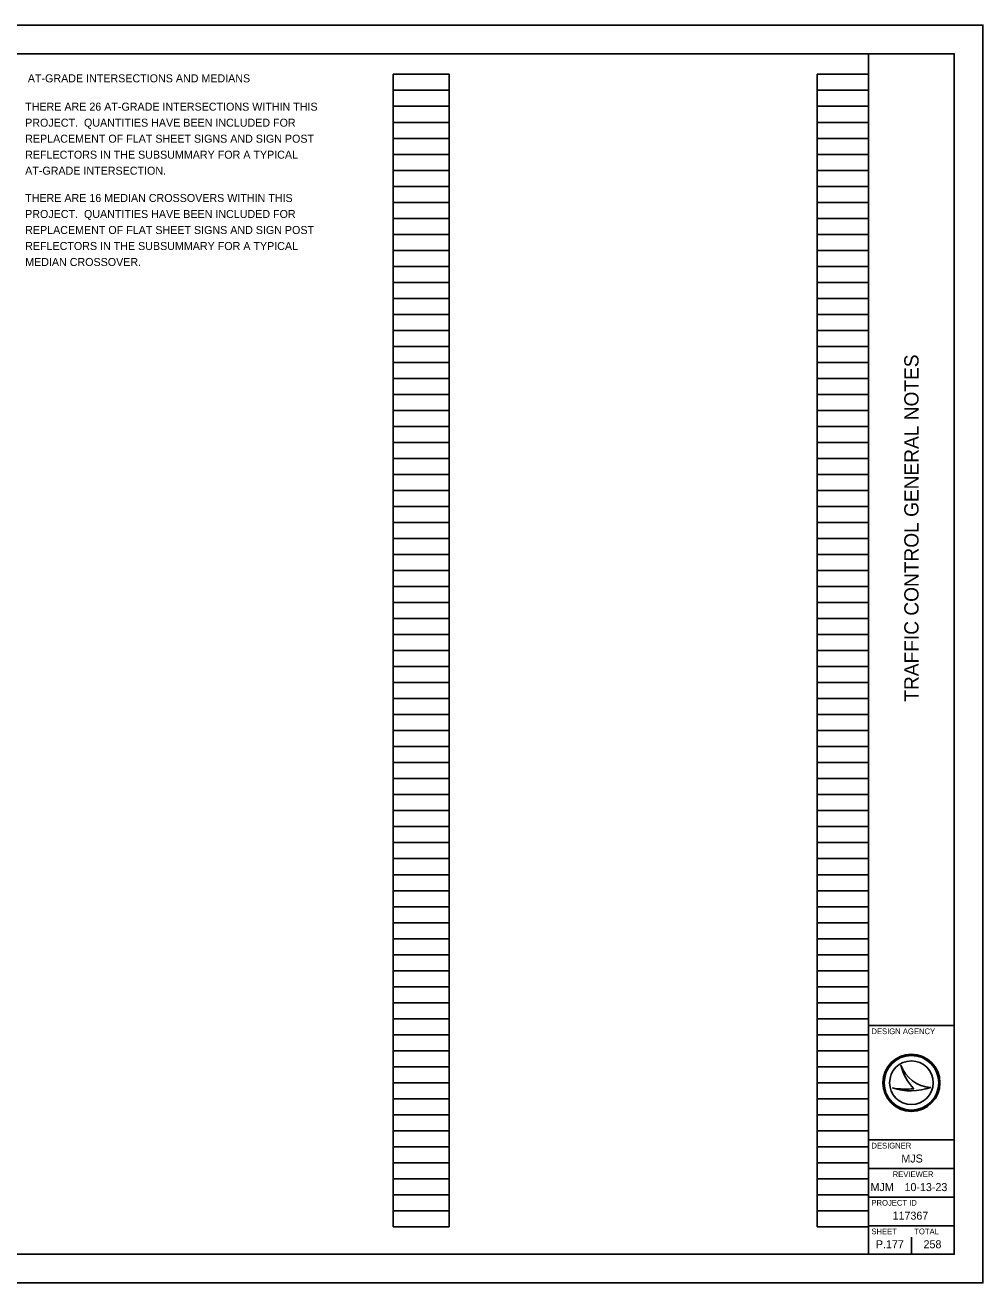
# Model space of a CAD drawing. Extents: x 0 to 34, y 0 to 22.
# Drawn here: x 17.24 to 34, y 0 to 22 of the extents above; entities that cross this region are included whole.
import ezdxf

# ---------------------------------------------------------------- set-up
doc = ezdxf.new("R2010")
doc.units = 0
for name, color, linetype in [('SH_Border', 7, 'Continuous'), ('SH_Cut_Line', 7, 'Continuous'), ('SH_Data', 7, 'Continuous'), ('TX_P_Misc', 7, 'Continuous')]:
    doc.layers.add(name, color=color, linetype=linetype)

msp = doc.modelspace()

# ---------------------------------------------------------------- linework, layer by layer
at = {"layer": 'SH_Border'}
for p, q in [((32, 0.5), (32, 21.5)), ((32, 4.5), (33.5, 4.5)), ((32, 2.5), (33.5, 2.5)), ((32, 2), (33.5, 2)), ((32, 1.5), (33.5, 1.5)), ((32, 1), (33.5, 1))]:
    msp.add_line(p, q, dxfattribs=at)
msp.add_lwpolyline([(1.5, 21.5), (33.5, 21.5), (33.5, 0.5), (1.5, 0.5)], close=True, dxfattribs=at)
at = {"layer": 'SH_Cut_Line'}
msp.add_lwpolyline([(0, 0), (34, 0), (34, 22), (0, 22)], close=True, dxfattribs=at)
at = {"layer": 'SH_Data'}
for p, q in [((23.68, 0.98), (23.68, 21.14)), ((23.68, 21.14), (24.66, 21.14)), ((24.66, 0.98), (24.66, 21.14)), ((31.1, 0.98), (31.1, 21.14)), ((31.1, 21.14), (32, 21.14)), ((32, 0.98), (32, 21.14)), ((23.68, 20.86), (24.66, 20.86)), ((31.1, 20.86), (32, 20.86)), ((23.68, 20.58), (24.66, 20.58)), ((31.1, 20.58), (32, 20.58)), ((23.68, 20.3), (24.66, 20.3)), ((31.1, 20.3), (32, 20.3)), ((23.68, 20.02), (24.66, 20.02)), ((31.1, 20.02), (32, 20.02)), ((23.68, 19.74), (24.66, 19.74)), ((31.1, 19.74), (32, 19.74)), ((23.68, 19.46), (24.66, 19.46)), ((31.1, 19.46), (32, 19.46)), ((23.68, 19.18), (24.66, 19.18)), ((31.1, 19.18), (32, 19.18)), ((23.68, 18.9), (24.66, 18.9)), ((31.1, 18.9), (32, 18.9)), ((23.68, 18.62), (24.66, 18.62)), ((31.1, 18.62), (32, 18.62)), ((23.68, 18.34), (24.66, 18.34)), ((31.1, 18.34), (32, 18.34)), ((23.68, 18.06), (24.66, 18.06)), ((31.1, 18.06), (32, 18.06)), ((23.68, 17.78), (24.66, 17.78)), ((31.1, 17.78), (32, 17.78)), ((23.68, 17.5), (24.66, 17.5)), ((31.1, 17.5), (32, 17.5)), ((23.68, 17.22), (24.66, 17.22)), ((31.1, 17.22), (32, 17.22)), ((23.68, 16.94), (24.66, 16.94)), ((31.1, 16.94), (32, 16.94)), ((23.68, 16.66), (24.66, 16.66)), ((31.1, 16.66), (32, 16.66)), ((23.68, 16.38), (24.66, 16.38)), ((31.1, 16.38), (32, 16.38)), ((23.68, 16.1), (24.66, 16.1)), ((31.1, 16.1), (32, 16.1)), ((23.68, 15.82), (24.66, 15.82)), ((31.1, 15.82), (32, 15.82)), ((23.68, 15.54), (24.66, 15.54)), ((31.1, 15.54), (32, 15.54)), ((23.68, 15.26), (24.66, 15.26)), ((31.1, 15.26), (32, 15.26)), ((23.68, 14.98), (24.66, 14.98)), ((31.1, 14.98), (32, 14.98)), ((23.68, 14.7), (24.66, 14.7)), ((31.1, 14.7), (32, 14.7)), ((23.68, 14.42), (24.66, 14.42)), ((31.1, 14.42), (32, 14.42)), ((23.68, 14.14), (24.66, 14.14)), ((31.1, 14.14), (32, 14.14)), ((23.68, 13.86), (24.66, 13.86)), ((31.1, 13.86), (32, 13.86)), ((23.68, 13.58), (24.66, 13.58)), ((31.1, 13.58), (32, 13.58)), ((23.68, 13.3), (24.66, 13.3)), ((31.1, 13.3), (32, 13.3)), ((23.68, 13.02), (24.66, 13.02)), ((31.1, 13.02), (32, 13.02)), ((23.68, 12.74), (24.66, 12.74)), ((31.1, 12.74), (32, 12.74)), ((23.68, 12.46), (24.66, 12.46)), ((31.1, 12.46), (32, 12.46)), ((23.68, 12.18), (24.66, 12.18)), ((31.1, 12.18), (32, 12.18)), ((23.68, 11.9), (24.66, 11.9)), ((31.1, 11.9), (32, 11.9)), ((23.68, 11.62), (24.66, 11.62)), ((31.1, 11.62), (32, 11.62)), ((23.68, 11.34), (24.66, 11.34)), ((31.1, 11.34), (32, 11.34)), ((23.68, 11.06), (24.66, 11.06)), ((31.1, 11.06), (32, 11.06)), ((23.68, 10.78), (24.66, 10.78)), ((31.1, 10.78), (32, 10.78)), ((23.68, 10.5), (24.66, 10.5)), ((31.1, 10.5), (32, 10.5)), ((23.68, 10.22), (24.66, 10.22)), ((31.1, 10.22), (32, 10.22)), ((23.68, 9.94), (24.66, 9.94)), ((31.1, 9.94), (32, 9.94)), ((23.68, 9.66), (24.66, 9.66)), ((31.1, 9.66), (32, 9.66)), ((23.68, 9.38), (24.66, 9.38)), ((31.1, 9.38), (32, 9.38)), ((23.68, 9.1), (24.66, 9.1)), ((31.1, 9.1), (32, 9.1)), ((23.68, 8.82), (24.66, 8.82)), ((31.1, 8.82), (32, 8.82)), ((23.68, 8.54), (24.66, 8.54)), ((31.1, 8.54), (32, 8.54)), ((23.68, 8.26), (24.66, 8.26)), ((31.1, 8.26), (32, 8.26)), ((23.68, 7.98), (24.66, 7.98)), ((31.1, 7.98), (32, 7.98)), ((23.68, 7.7), (24.66, 7.7)), ((31.1, 7.7), (32, 7.7)), ((23.68, 7.42), (24.66, 7.42)), ((31.1, 7.42), (32, 7.42)), ((23.68, 7.14), (24.66, 7.14)), ((31.1, 7.14), (32, 7.14)), ((23.68, 6.86), (24.66, 6.86)), ((31.1, 6.86), (32, 6.86)), ((23.68, 6.58), (24.66, 6.58)), ((31.1, 6.58), (32, 6.58)), ((23.68, 6.3), (24.66, 6.3)), ((31.1, 6.3), (32, 6.3)), ((23.68, 6.02), (24.66, 6.02)), ((31.1, 6.02), (32, 6.02)), ((23.68, 5.74), (24.66, 5.74)), ((31.1, 5.74), (32, 5.74)), ((23.68, 5.46), (24.66, 5.46)), ((31.1, 5.46), (32, 5.46)), ((23.68, 5.18), (24.66, 5.18)), ((31.1, 5.18), (32, 5.18)), ((23.68, 4.9), (24.66, 4.9)), ((31.1, 4.9), (32, 4.9)), ((23.68, 4.62), (24.66, 4.62)), ((31.1, 4.62), (32, 4.62)), ((23.68, 4.34), (24.66, 4.34)), ((31.1, 4.34), (32, 4.34)), ((23.68, 4.06), (24.66, 4.06)), ((31.1, 4.06), (32, 4.06)), ((23.68, 3.78), (24.66, 3.78)), ((31.1, 3.78), (32, 3.78)), ((32.567, 3.81), (32.567, 3.81)), ((23.68, 3.5), (24.66, 3.5)), ((31.1, 3.5), (32, 3.5)), ((32.417, 3.41), (32.417, 3.41)), ((32.75, 3.5), (32.75, 3.5)), ((33.087, 3.419), (33.087, 3.419)), ((23.68, 3.22), (24.66, 3.22)), ((31.1, 3.22), (32, 3.22)), ((23.68, 2.94), (24.66, 2.94)), ((31.1, 2.94), (32, 2.94)), ((23.68, 2.66), (24.66, 2.66)), ((31.1, 2.66), (32, 2.66)), ((23.68, 2.38), (24.66, 2.38)), ((31.1, 2.38), (32, 2.38)), ((23.68, 2.1), (24.66, 2.1)), ((31.1, 2.1), (32, 2.1)), ((23.68, 1.82), (24.66, 1.82)), ((31.1, 1.82), (32, 1.82)), ((23.68, 1.54), (24.66, 1.54)), ((31.1, 1.54), (32, 1.54)), ((23.68, 1.26), (24.66, 1.26)), ((31.1, 1.26), (32, 1.26)), ((23.68, 0.98), (24.66, 0.98)), ((31.1, 0.98), (32, 0.98)), ((32.375, 0.675), (32.375, 0.675)), ((32.75, 0.5), (32.75, 0.8))]:
    msp.add_line(p, q, dxfattribs=at)
for radius in [0.5, 0.477, 0.477, 0.382]:
    msp.add_circle((32.75, 3.5), radius, dxfattribs=at)
for centre, radius, start, end in [((33.116, 3.998), 0.58, 198.9257, 198.9319), ((33.347, 3.97), 0.796, 191.6379, 191.6421), ((33.116, 3.998), 0.58, 198.9319, 267.1657), ((33.347, 3.97), 0.796, 191.6421, 226.0947), ((32.739, 4.37), 1.013, 251.4576, 290.0832), ((32.648, 4.654), 1.266, 259.4964, 259.4995), ((32.739, 4.37), 1.013, 251.4527, 251.4576), ((32.648, 4.654), 1.266, 259.4995, 276.6672)]:
    msp.add_arc(centre, radius, start, end, dxfattribs=at)

# ---------------------------------------------------------------- texts
msp.add_text('TRAFFIC CONTROL GENERAL NOTES', height=0.25, rotation=90, dxfattribs=at).set_placement((32.875, 10.166))
for s, height, p in [('DESIGN AGENCY', 0.1, (32.05, 4.35)), ('DESIGNER', 0.1, (32.05, 2.35)), ('MJS', 0.14, (32.574, 2.105)), ('REVIEWER', 0.1, (32.422, 1.85)), ('MJM', 0.14, (32.035, 1.605)), ('10-13-23', 0.14, (32.629, 1.605)), ('PROJECT ID', 0.1, (32.05, 1.35)), ('117367', 0.14, (32.42, 1.105)), ('SHEET', 0.1, (32.05, 0.85)), ('TOTAL', 0.1, (32.8, 0.85)), ('P.177', 0.14, (32.128, 0.605)), ('258', 0.14, (32.962, 0.605))]:
    msp.add_text(s, height=height, dxfattribs=at).set_placement(p)
at = {"layer": 'TX_P_Misc'}
for s, p in [('AT-GRADE INTERSECTIONS AND MEDIANS', (17.288, 21)), ('THERE ARE 26 AT-GRADE INTERSECTIONS WITHIN THIS', (17.241, 20.504)), ('PROJECT.  QUANTITIES HAVE BEEN INCLUDED FOR', (17.241, 20.224)), ('REPLACEMENT OF FLAT SHEET SIGNS AND SIGN POST', (17.241, 19.944)), ('REFLECTORS IN THE SUBSUMMARY FOR A TYPICAL', (17.241, 19.664)), ('AT-GRADE INTERSECTION.', (17.241, 19.384)), ('THERE ARE 16 MEDIAN CROSSOVERS WITHIN THIS', (17.241, 18.907)), ('PROJECT.  QUANTITIES HAVE BEEN INCLUDED FOR', (17.241, 18.627)), ('REPLACEMENT OF FLAT SHEET SIGNS AND SIGN POST', (17.241, 18.347)), ('REFLECTORS IN THE SUBSUMMARY FOR A TYPICAL', (17.241, 18.067)), ('MEDIAN CROSSOVER.', (17.241, 17.787))]:
    msp.add_text(s, height=0.14, dxfattribs=at).set_placement(p)

doc.saveas('drawing.dxf')
